// Mitsubishi GX Works2 project: 三菱习题46(空压机控制)(1)   PLC: FX3U/FX3UC

PROGRAM MAIN
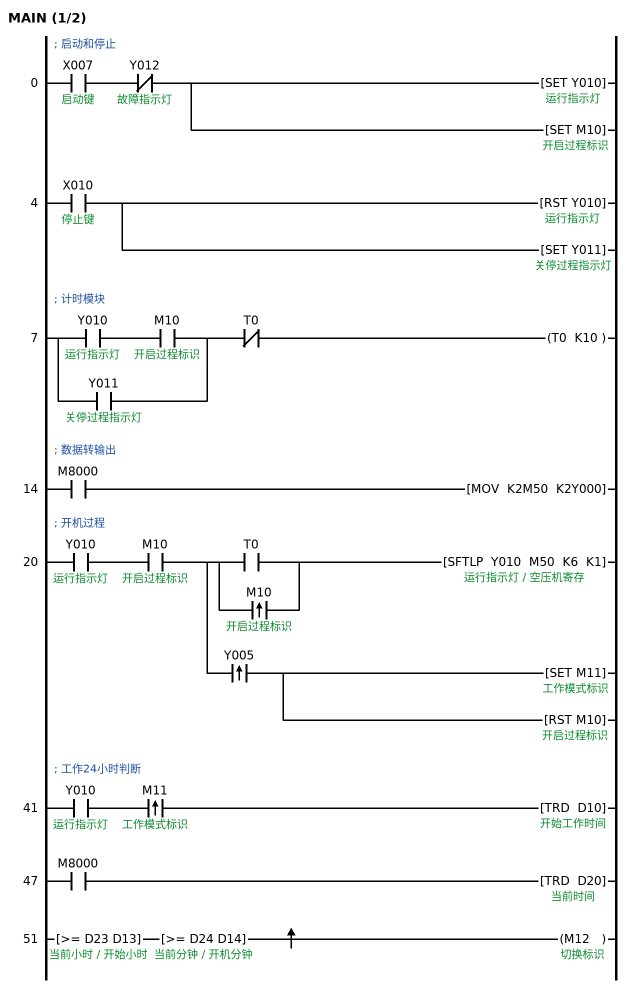
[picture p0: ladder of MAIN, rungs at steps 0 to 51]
; 启动和停止
0     LD      X007  ; 启动键
      ANI     Y012  ; 故障指示灯
      SET     Y010  ; 运行指示灯
      SET     M10  ; 开启过程标识
4     LD      X010  ; 停止键
      RST     Y010  ; 运行指示灯
      SET     Y011  ; 关停过程指示灯
; 计时模块
7     LD      Y010  ; 运行指示灯
      AND     M10  ; 开启过程标识
      OR      Y011  ; 关停过程指示灯
      ANI     T0
      OUT     T0 K10
; 数据转输出
14    LD      M8000
      MOV     K2M50 K2Y000  ; 空压机寄存 / 空压机输出
; 开机过程
20    LD      Y010  ; 运行指示灯
      AND     M10  ; 开启过程标识
      MPS
      LD      T0
      ORP     M10  ; 开启过程标识
      ANB
      SFTLP   Y010 M50 K6 K1
      MPP
      ANDP    Y005
      SET     M11  ; 工作模式标识
      RST     M10  ; 开启过程标识
; 工作24小时判断
41    LD      Y010  ; 运行指示灯
      ANDP    M11  ; 工作模式标识
      TRD     D10  ; 开始工作时间
47    LD      M8000
      TRD     D20  ; 当前时间
51    LD>=    D23 D13  ; 当前小时 / 开始小时
      AND>=   D24 D14  ; 当前分钟 / 开机分钟
      MEP
      OUT     M12  ; 切换标识
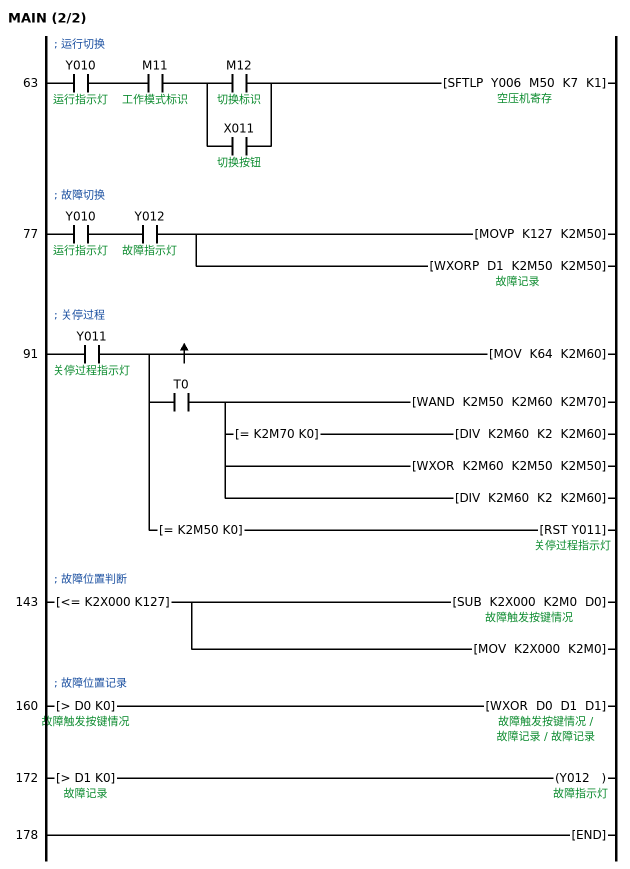
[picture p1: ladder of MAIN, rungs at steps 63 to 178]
; 运行切换
63    LD      Y010  ; 运行指示灯
      AND     M11  ; 工作模式标识
      LD      M12  ; 切换标识
      OR      X011  ; 切换按钮
      ANB
      SFTLP   Y006 M50 K7 K1
        [note] 用Y6的数据做位移
; 故障切换
77    LD      Y010  ; 运行指示灯
      AND     Y012  ; 故障指示灯
      MOVP    K127 K2M50
      WXORP   D1 K2M50 K2M50  ; 故障记录
; 关停过程
91    LD      Y011  ; 关停过程指示灯
      MPS
      MEP
      MOV     K64 K2M60  ; 关停位置
        [note] 设定第七位为关停起始位
      MRD
      AND     T0
      WAND    K2M50 K2M60 K2M70  ; 关停校验
        [note] 检测关停位置设备是否开启
      MPS
      AND=    K2M70 K0  ; 关停校验
      DIV     K2M60 K2 K2M60
        [note] 如果当前位置未开启，直接右移
      MPP
      WXOR    K2M60 K2M50 K2M50
        [note] 关停关停位上的机器
      DIV     K2M60 K2 K2M60
        [note] 关停位置右移一位
      MPP
      AND=    K2M50 K0  ; 空压机寄存
      RST     Y011  ; 关停过程指示灯
; 故障位置判断
143   LD<=    K2X000 K127
      SUB     K2X000 K2M0 D0  ; 按键记录 / 故障触发按键情况
        [note] k2x0-k2m0，得出按键情况
      MOV     K2X000 K2M0
        [note] 上个周期按键记录
; 故障位置记录
160   LD>     D0 K0  ; 故障触发按键情况
      WXOR    D0 D1 D1
        [note] 把故障按键转换到故障记录
172   LD>     D1 K0  ; 故障记录
      OUT     Y012  ; 故障指示灯
178   END
END_PROGRAM

// device comments not shown above
X012  ; 停止
D2  ; 灯组数据
D12  ; 日期
D17  ; 日期暂存
